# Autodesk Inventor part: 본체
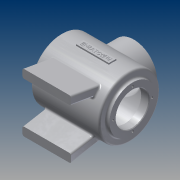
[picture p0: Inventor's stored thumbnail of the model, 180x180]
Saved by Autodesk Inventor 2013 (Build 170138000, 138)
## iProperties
Created: 2015-01
Part Number: 본체
Material: 알루미늄 6061
Document SubType Name: Modeling
Designer: cad8
Density: 2.71 g/cm^3
Mass: 1021.36 g
Surface Area: 1061.35 cm^2
Volume: 376.886 cm^3
Author: cad8
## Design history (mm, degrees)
sketch "스케치1"
  geometry: L1 (0, 0)-(122, 0); L2 (0, 27)-(0, 38); L3 (0, 38)-(5, 38); L4 (5, 38)-(5, 50); L5 (5, 50)-(117, 50); L6 (117, 50)-(117, 38); L7 (117, 38)-(122, 38); L8 (122, 38)-(122, 27); L9 (122, 27)-(109, 27); L10 (109, 27)-(109, 45); L11 (109, 45)-(12, 45); L12 (12, 45)-(12, 27); L13 (12, 27)-(0, 27)
  constraints: 26 end point, 5 parallel, 5 perpendicular, 2 collinear, 1 horizontal
  dimensions: "d0" = 122 distance of L1.start L1.end; "d1" = 100 diameter of L5 L1; "d2" = 54 diameter of L13 L1; "d3" = 90 diameter of L11 L1; "d4" = 54 diameter of L9 L1; "d9" = 76 diameter of L3 L1; "d10" = 76 diameter of L7 L1; "d11" = 122 distance between parallel lines of L8 L2; "d12" = 97 distance of L10.end L11.end
revolve "회전1" sketch "스케치1" stored, may be unused: angle "d13" = 90 deg
node "작업축1"
node "작업 평면1"
sketch "스케치2"
  geometry: L1 (-48, -80)-(-34, -80); L2 (-34, -80)-(-26.941, -39.965); L3 (-38.311, -25.053)-(-48, -80); L4 (34, -80)-(48, -80); L5 (26.786, -39.089)-(34, -80); L6 (48, -80)-(38.458, -25.885); L7 (38.458, -25.885)-(26.786, -39.089); L8 (-38.311, -25.053)-(-26.941, -39.965); 1 further point
  constraints: 16 end point, 1 collinear, 1 horizontal, 1 parallel
  dimensions: "d14" = 14 distance of L1.start L1.end; "d16" = 80 distance from line of L1 point (0, 0); "d17" = 80 deg angle of L1 L2; "d18" = 14 distance of L4.start L4.end; "d19" = 100 deg angle of L4 L6; "d20" = 80 deg angle of L4 L5; "d21" = 80 distance from line of L4 point (0, 0); "d22" = 96 distance of L1.start L4.end; "d23" = 48 horizontal distance of L1.start point (0, 0)
extrude "돌출1" join sketch "스케치2" stored distance "d24" = 80; taper "d25" = 0 deg
node "작업 평면3"
  node "작업 평면2"
sketch "스케치4"
  geometry: C1 r 38 at (1, 0); 1 further point
  constraints: 1 centre point
  dimensions: "d28" = 62 distance of C1.centre point (-61, 0); "d29" = 76 diameter of C1
extrude "돌출2" join sketch "스케치4" stored distance "d30" = 80; taper "d31" = 0 deg
node "작업 평면6"
  node "작업 평면5"
sketch "스케치6"
  geometry: L1 (-26, 6)-(28, 6); L2 (28, 6)-(28, -6); L3 (28, -6)-(-26, -6); L4 (-26, -6)-(-26, 6); L5 (-37, 62)-(39, 62) reference; L6 (1, 62)-(1, 50.11); 1 further point
  constraints: 10 end point, 2 parallel, 2 perpendicular, 1 horizontal, 1 midpoint
  dimensions: "d34" = 54 distance of L1.start L1.end; "d36" = 12 distance of L3.end L1.start; "d37" = 6 distance from line of point (-61, 0) L1; "d38" = 27 distance between parallel lines of L6 L4
extrude "돌출3" join sketch "스케치6" stored distance "d39" = 80; taper "d40" = 0 deg
sketch "스케치7"
  geometry: C1 r 38 at (0, 0) reference; C2 r 27 at (0, 0); 1 further point
  constraints: 1 centre point, 1 coincident
  dimensions: "d41" = 54 diameter of C2
extrude "돌출4" cut sketch "스케치7" stored distance "d43" = 80; taper "d44" = 0 deg
sketch "스케치8"
  geometry: C1 r 38 at (0, 0) reference; A1 r 32 centre (0, 0) between (0, 32) and (-32, 0); 3 further points
  constraints: 4 point on circle, 1 centre point, 1 coincident
  dimensions: "d45" = 64 diameter of A1
hole "구멍1" sketch "스케치8" at (0, 32), (-32, 0), (0, -32), (32, 0) diameter "d47" = 3.242; stored, may be unused: countersink angle "d51" = 90 deg, drill point angle "d53" = 118 deg; dims "d48" = 8, "d49" = 4, "d50" = 2, "d52" = 10
sketch "스케치10"
  geometry: C1 r 27 at (0, 0) reference; A1 r 32 centre (0, 0) between (0, 32) and (-32, 0); 2 further points
  constraints: 4 point on circle, 1 centre point, 1 coincident
  dimensions: "d57" = 64 diameter of A1
hole "구멍2" sketch "스케치10" at (0, 32), (-32, 0), (0, -32), (32, 0) diameter "d59" = 3.242; stored, may be unused: countersink angle "d63" = 90 deg, drill point angle "d65" = 118 deg; dims "d60" = 8, "d61" = 4, "d62" = 2, "d64" = 10
node "작업 평면7"
sketch "스케치12"
  geometry: L1 (-37, 62)-(39, 62) reference; L2 (1, 62)-(1, 53.754); 2 further points
  constraints: 2 end point, 1 midpoint, 1 perpendicular, 1 other
  dimensions: "d67" = 0 vertical distance of point (1, 0) point (-61, 0); "d68" = 0 distance from line of L2 point (1, 0)
feature "엠보싱1" sketch "스케치12" dims "d69" = 0.5, "d70" = 0
chamfer "모따기1" distance "d71" = 1; stored, may be unused: second distance "d72" = 2, angle "d73" = 45 deg
fillet "모깎기1" dims "d74" = 3
fillet "모깎기2" dims "d75" = 3
fillet "모깎기3" dims "d76" = 3
fillet "모깎기4" dims "d77" = 3
node "솔리드1"
mirror "대칭1"
node "작업 평면4"
other parameters: "d26" = 0, "d27" = 62, "d32" = 0, "d33" = 2
